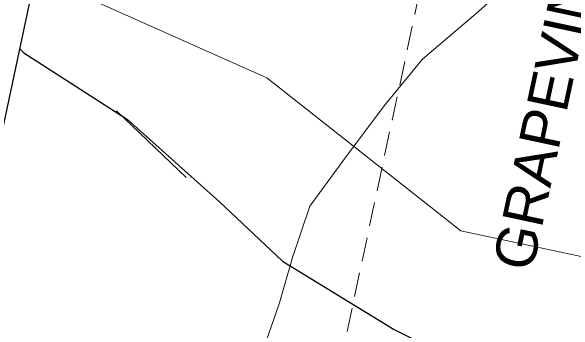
# Model space of a CAD drawing. Extents: x 2363411 to 2369126, y 6976878 to 6988319.
# Drawn here: x 2365730.4 to 2365871.2, y 6977159 to 6977238.8 of the extents above; entities that cross this region are included whole.
import ezdxf

# ---------------------------------------------------------------- set-up
doc = ezdxf.new("R2010")
doc.units = 0
doc.header["$LTSCALE"] = 2
doc.linetypes.add('MEDIUM_DASHED', pattern=[4.5, 3, -1.5])
doc.layers.add('62', color=7, linetype='Continuous', lineweight=13)
doc.layers.add('63', color=7, linetype='Continuous', lineweight=13)

msp = doc.modelspace()

# ---------------------------------------------------------------- linework, layer by layer
at = {"layer": '62', "lineweight": 25}
for p, q in [((2365678.211, 6976974.92), (2365772.152, 6977414.588)), ((2365826.23, 6977159.266), (2365835.918, 6977154.55))]:
    msp.add_line(p, q, dxfattribs=at)
at = {"layer": '62', "linetype": 'MEDIUM_DASHED'}
msp.add_line((2365864.629, 6977393.47), (2365770.962, 6976955.102), dxfattribs=at)
at = {"layer": '62'}
for p, q in [((2365774.247, 6977197.271), (2365756.773, 6977213.916)), ((2365873.084, 6977177.51), (2365842.962, 6977183.947))]:
    msp.add_line(p, q, dxfattribs=at)
for points in [[(2365745.602, 6977025.615), (2365742.995, 6977037.011), (2365744.177, 6977051.369), (2365754.758, 6977065.562), (2365757.967, 6977076.059), (2365767.656, 6977087.91), (2365774.215, 6977096.102), (2365778.852, 6977103.376), (2365783.338, 6977114.034), (2365786.122, 6977122.873), (2365789.101, 6977134.663), (2365791.544, 6977148.682), (2365797.575, 6977165.918), (2365800.831, 6977177.279), (2365805.2, 6977190.083), (2365814.728, 6977203.211), (2365824.115, 6977215.605), (2365833.318, 6977226.804), (2365847.376, 6977238.756), (2365856.409, 6977246.882), (2365866.274, 6977257.086), (2365874.425, 6977262.384)], [(2365842.962, 6977183.947), (2365794.385, 6977222.168), (2365736.964, 6977247.854)]]:
    msp.add_lwpolyline(points, dxfattribs=at)
at = {"layer": '62', "lineweight": 25}
msp.add_lwpolyline([(2365732.591, 6977229.435), (2365733.581, 6977228.463), (2365759.574, 6977211.728), (2365782.597, 6977191.229), (2365798.344, 6977176.407), (2365826.23, 6977159.266)], dxfattribs=at)
at = {"layer": '63', "lineweight": 25}
for p, q in [((2365678.211, 6976974.92), (2365772.152, 6977414.588)), ((2365826.23, 6977159.266), (2365835.918, 6977154.55))]:
    msp.add_line(p, q, dxfattribs=at)
at = {"layer": '63', "linetype": 'MEDIUM_DASHED'}
msp.add_line((2365864.629, 6977393.47), (2365770.962, 6976955.102), dxfattribs=at)
at = {"layer": '63'}
for p, q in [((2365774.247, 6977197.271), (2365756.773, 6977213.916)), ((2365873.084, 6977177.51), (2365842.962, 6977183.947))]:
    msp.add_line(p, q, dxfattribs=at)
for points in [[(2365745.602, 6977025.615), (2365742.995, 6977037.011), (2365744.177, 6977051.369), (2365754.758, 6977065.562), (2365757.967, 6977076.059), (2365767.656, 6977087.91), (2365774.215, 6977096.102), (2365778.852, 6977103.376), (2365783.338, 6977114.034), (2365786.122, 6977122.873), (2365789.101, 6977134.663), (2365791.544, 6977148.682), (2365797.575, 6977165.918), (2365800.831, 6977177.279), (2365805.2, 6977190.083), (2365814.728, 6977203.211), (2365824.115, 6977215.605), (2365833.318, 6977226.804), (2365847.376, 6977238.756), (2365856.409, 6977246.882), (2365866.274, 6977257.086), (2365874.425, 6977262.384)], [(2365842.962, 6977183.947), (2365794.385, 6977222.168), (2365736.964, 6977247.854)]]:
    msp.add_lwpolyline(points, dxfattribs=at)
at = {"layer": '63', "lineweight": 25}
msp.add_lwpolyline([(2365732.591, 6977229.435), (2365733.581, 6977228.463), (2365759.574, 6977211.728), (2365782.597, 6977191.229), (2365798.344, 6977176.407), (2365826.23, 6977159.266)], dxfattribs=at)

# ---------------------------------------------------------------- texts
at = {"layer": '62', "width": 1.05}
msp.add_text('GRAPEVINE', height=10.21, rotation=77.939, dxfattribs=at).set_placement((2365860.825, 6977173.432))
at = {"layer": '63', "width": 1.05}
msp.add_text('GRAPEVINE', height=10.21, rotation=77.939, dxfattribs=at).set_placement((2365860.825, 6977173.432))

doc.saveas('drawing.dxf')
